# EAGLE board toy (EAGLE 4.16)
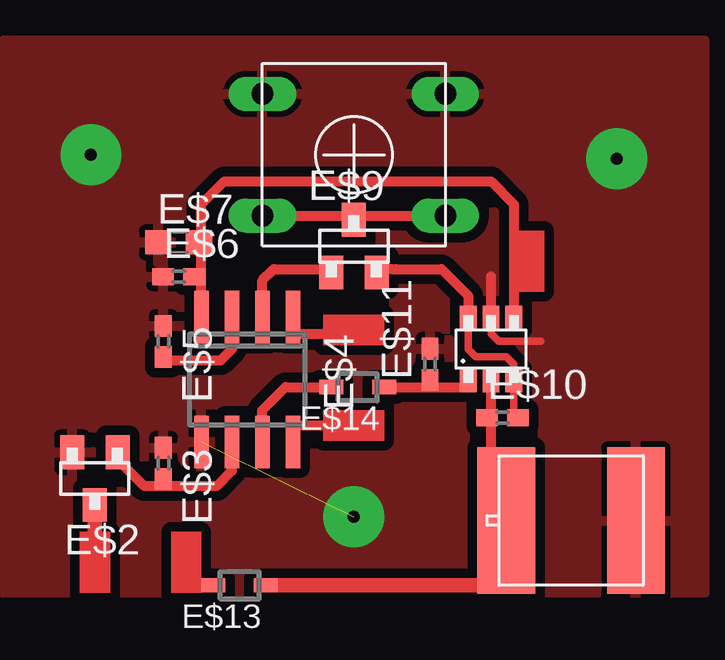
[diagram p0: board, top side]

No outline drawn. Coordinates in mm, seen from the top.
Copper layers (1*16): Top 0.035mm / dielectric 1.5mm / Bottom 0.035mm
Design rules "default": minimum track width 10mil, minimum drill 24mil, track to track 8mil, track to pad 8mil, pad to pad 8mil, via to via 8mil, smd to smd 8mil, copper to edge 40mil, drill to drill 8mil, minimum pad ring 10mil, minimum via ring 8mil, stop-mask expansion 4mil, vias tented up to drill 0mil, thermal gap 10mil

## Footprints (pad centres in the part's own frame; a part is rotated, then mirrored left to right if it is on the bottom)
R = smd 6.1 x 2.4: P$1 0,2.7; P$2 0,-2.7
SOT23 = smd 1 x 1.4: 1 -0.95,-1.1; 2 0.95,-1.1; 3 0,1.1
C0402 = smd 0.9 x 0.7: 1 -0.65,0; 2 0.65,0
SO08 = smd 0.6 x 2.2: 1 -1.905,-2.6; 2 -0.635,-2.6; 3 0.635,-2.6; 4 1.905,-2.6; 5 1.905,2.6; 6 0.635,2.6; 7 -0.635,2.6; 8 -1.905,2.6
C0603 = smd 1.1 x 1: 1 -0.85,0; 2 0.85,0
SUPERSOT-6 = smd 0.7 x 1: P$1 -0.95,1.3; P$2 0,1.3; P$3 0.95,1.3; P$4 -0.95,-1.3; P$5 0,-1.3; P$6 0.95,-1.3
SW_TACT_KSL4 = drill 0.9 long: 1 -3.81,2.54; 2 -3.81,-2.54; 3 3.81,-2.54; 4 3.81,2.54
SOD323 = smd 1 x 0.6: 1 -1.1,0; 2 1.1,0

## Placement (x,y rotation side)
E$1  [R]  9.05,3.02 90 top
E$2  [SOT23]  -10.8,4.76 180 top
E$3  [C0402]  -7.94,5.4 270 top
E$4  [SO08]  -4.45,8.89 180 top
E$5  [C0402]  -7.94,10.48 270 top
E$6  [C0402]  -7.3,13.18 0 top
E$7  [C0603]  -7.3,14.61 0 top
E$8  [SUPERSOT-6]  5.71,10.16 0 top
E$9  [SOT23]  0,14.45 0 top
E$10  [C0402]  6.19,7.3 0 top
E$11  [C0402]  3.18,9.53 90 top
E$12  [SW_TACT_KSL4]  0,18.26 0 top
E$13  [SOD323]  -4.76,0.32 180 top
E$14  [SOD323]  0.16,8.57 180 top

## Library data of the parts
E$1 = vishay
E$2 E$8 E$9 E$12 = sb
E$3-E$7 E$10 E$11 E$13 E$14 = ref-packages

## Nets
GND: E$1.P$2 E$2.2 E$3.1 E$4.5 E$5.1 E$6.1 E$7.1 E$11.2 E$12.1 E$12.4

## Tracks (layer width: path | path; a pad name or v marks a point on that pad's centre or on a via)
GND  (via drill 0.5 pad 2.54)  (1 unrouted)
  Top 0.305: 5.71,11.59 5.71,10.79 6.03,10.48 7.78,10.48
  Top 0.406: 5.71,11.59 5.71,13.18
  other vias: 0,3.17 -10.95,18.26 10.95,18.1
  pour Top (isolate 0.406): -14.61,0 -14.61,23.02 14.61,23.02 14.61,0
S$2
  Top 0.406: 4.76,11.59 4.76,12.38 3.65,13.49 1.75,13.49 1.59,13.49 0.95,13.49
S$3
  Top 0.61: -3.65,0.32 5.4,0.32
S$4
  Top 0.305: 6.67,7.14 6.67,9.53 6.35,9.84 5.08,9.84 4.76,10.16 4.76,11.43
S$5
  Top 0.406: -1.27,8.57 -2.86,8.57 -3.81,7.62 -3.81,6.35
S$6
  Top 0.406: -7.94,9.68 -5.56,9.68 -5.08,10.16 -5.08,11.43
S$7
  Top 0.406: -2.54,6.99 -0.64,6.99
S$8
  Top 0.406: -2.54,10.79 -0.64,10.79
S$9
  Top 0.61: -6.67,0.32 -5.87,0.32
S$10
  Top 0.406: 5.71,1.91 5.71,8.89
S$11
  Top 0.406: -3.81,15.72 3.97,15.72
S$12
  Top 0.406: -3.81,11.43 -3.81,13.02 -3.33,13.49 -0.95,13.49
S$13
  Top 0.406: 1.11,8.57 4.76,8.57
S$14
  Top 0.406: -5.08,6.35 -5.08,5.08 -5.71,4.45 -8.73,4.45 -10,5.71
S$15
  Top 0.61: -10.79,3.17 -10.79,1.91
S$16
  Top 0.406: 6.67,11.43 6.67,16.19 5.71,17.14 -5.4,17.14 -6.35,16.19 -6.35,11.43
(copper drawn outside any net)
  shapes: Top area x5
